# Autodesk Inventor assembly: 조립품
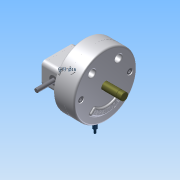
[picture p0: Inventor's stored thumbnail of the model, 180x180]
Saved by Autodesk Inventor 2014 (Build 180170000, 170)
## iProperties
Created: 2015-05
Part Number: 조립품
Document SubType Name: Assembly
Designer: Administrator
Author: Administrator
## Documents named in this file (15)
- C:\Documents and Settings\Administrator\바탕 화면\350406V1035\조립품.iam
- C:\Documents and Settings\Administrator\바탕 화면\350406V1035\본체.ipt
- C:\Documents and Settings\Administrator\바탕 화면\350406V1035\커버.ipt
- C:\Documents and Settings\Administrator\바탕 화면\350406V1035\M 10 x 35.ipt
- C:\Documents and Settings\Administrator\바탕 화면\350406V1035\커버2.ipt
- C:\Documents and Settings\Administrator\바탕 화면\350406V1035\베어링62_22.ipt
- C:\Documents and Settings\Administrator\바탕 화면\350406V1035\축.ipt
- C:\Documents and Settings\Administrator\바탕 화면\350406V1035\M 5 x 12.ipt
- C:\Documents and Settings\Administrator\바탕 화면\350406V1035\멈춤링.ipt
- C:\Documents and Settings\Administrator\바탕 화면\350406V1035\슬라이더2.ipt
- C:\Documents and Settings\Administrator\바탕 화면\350406V1035\슬라이더.ipt
- C:\Documents and Settings\Administrator\바탕 화면\350406V1035\부시.ipt
- C:\Documents and Settings\Administrator\바탕 화면\350406V1035\평행핀.ipt
- C:\Documents and Settings\Administrator\바탕 화면\350406V1035\스프링-[가변].ipt
- C:\Documents and Settings\Administrator\바탕 화면\350406V1035\슬라이더3.ipt
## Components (5 placed, 3 different names)
1. KS B 1320 B B 5 x  20:1
2. M 10 x 35:1
3. M 10 x 35:2
4. M 5 x 12:1
5. M 5 x 12:2
